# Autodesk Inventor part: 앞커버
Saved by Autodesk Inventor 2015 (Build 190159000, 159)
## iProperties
Created: 2025-08
Part Number: 앞커버
Material: 일반
Document SubType Name: Modeling
Designer: user
Density: 1 g/cm^3
Appearance: 기본값
Author: user
Author: jhkim
Creation Date: 2025-08-05
Sending System: Autodesk Inventor 2026
Preprocessor: ST-DEVELOPER v20.1
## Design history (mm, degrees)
node "앞커버1"
node "솔리드1"
node "기준1"
